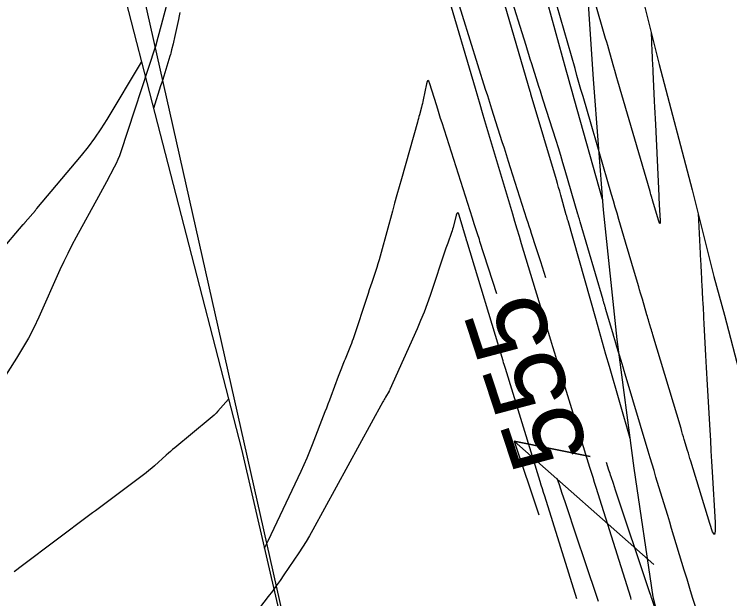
# Model space of a CAD drawing. Extents: x 954385 to 988206, y 1868364 to 1924553.
# Drawn here: x 957857.8 to 957913, y 1919566.3 to 1919611.4 of the extents above; entities that cross this region are included whole.
import ezdxf

# ---------------------------------------------------------------- set-up
doc = ezdxf.new("R2010")
doc.units = 0
for name, color, linetype in [('13', 7, 'Continuous'), ('16', 7, 'Continuous'), ('24', 7, 'Continuous'), ('26', 7, 'Continuous'), ('5', 7, 'Continuous'), ('6', 7, 'Continuous'), ('7', 7, 'Continuous'), ('Default', 7, 'Continuous')]:
    doc.layers.add(name, color=color, linetype=linetype)

msp = doc.modelspace()

# ---------------------------------------------------------------- linework, layer by layer
at = {"layer": '13'}
for points in [[(957852.935, 1919588.707), (957858.454, 1919595.175), (957858.462, 1919595.184), (957858.47, 1919595.193), (957858.478, 1919595.201), (957858.486, 1919595.21), (957858.52, 1919595.243), (957858.528, 1919595.252), (957858.536, 1919595.26), (957858.543, 1919595.27), (957858.55, 1919595.279), (957858.58, 1919595.319), (957858.587, 1919595.329), (957858.595, 1919595.339), (957858.602, 1919595.348), (957858.61, 1919595.358), (957859.394, 1919596.277), (957859.405, 1919596.289), (957859.414, 1919596.301), (957859.424, 1919596.313), (957859.433, 1919596.326), (957859.469, 1919596.377), (957859.479, 1919596.389), (957859.488, 1919596.402), (957859.498, 1919596.414), (957859.508, 1919596.426), (957862.946, 1919600.51), (957863.486, 1919601.177), (957863.997, 1919601.864), (957864.482, 1919602.57), (957864.938, 1919603.297), (957867.595, 1919607.714)], [(957874.297, 1919581.701), (957873.487, 1919580.766), (957873.349, 1919580.613), (957873.205, 1919580.467), (957873.055, 1919580.327), (957872.898, 1919580.193), (957870.15, 1919577.935), (957869.985, 1919577.798), (957869.821, 1919577.659), (957869.66, 1919577.518), (957869.499, 1919577.375), (957868.584, 1919576.55), (957868.376, 1919576.367), (957868.165, 1919576.188), (957867.949, 1919576.014), (957867.73, 1919575.844), (957866.108, 1919574.614), (957865.901, 1919574.458), (957865.693, 1919574.302), (957865.485, 1919574.147), (957865.277, 1919573.992), (957864.442, 1919573.375), (957864.233, 1919573.221), (957864.025, 1919573.066), (957863.817, 1919572.91), (957863.609, 1919572.755), (957858.39, 1919568.839), (957857.754, 1919568.363)]]:
    msp.add_lwpolyline(points, dxfattribs=at)
at = {"layer": '16'}
for points in [[(957890.519, 1919706.211), (957891.799, 1919696.25), (957893.016, 1919686.274), (957894.336, 1919676.322), (957895.78, 1919666.397), (957897.186, 1919656.464), (957898.672, 1919646.548), (957899.744, 1919636.541), (957900.425, 1919631.907), (957901.213, 1919626.621), (957901.79, 1919616.502), (957902.451, 1919606.402), (957903.226, 1919596.327), (957904.28, 1919586.315), (957905.605, 1919576.364), (957907.064, 1919566.442), (957908.777, 1919559.571)], [(957871.417, 1919619.226), (957868.747, 1919609.237), (957868.743, 1919609.221), (957868.739, 1919609.206), (957868.735, 1919609.19), (957868.732, 1919609.174), (957868.714, 1919609.093), (957868.711, 1919609.079), (957868.707, 1919609.065), (957868.7, 1919609.038), (957868.699, 1919609.031), (957868.697, 1919609.024), (957868.694, 1919609.018), (957868.692, 1919609.011), (957868.668, 1919608.946), (957868.663, 1919608.933), (957868.659, 1919608.92), (957868.654, 1919608.907), (957868.65, 1919608.894), (957865.986, 1919600.8), (957865.879, 1919600.496), (957865.76, 1919600.198), (957865.628, 1919599.905), (957865.485, 1919599.617), (957864.886, 1919598.476), (957864.736, 1919598.191), (957864.584, 1919597.907), (957864.431, 1919597.623), (957864.276, 1919597.341), (957862.547, 1919594.206), (957862.213, 1919593.586), (957861.892, 1919592.96), (957861.585, 1919592.327), (957861.291, 1919591.688), (957859.653, 1919588.031), (957859.269, 1919587.215), (957858.856, 1919586.415), (957858.414, 1919585.63), (957857.943, 1919584.862), (957851.753, 1919575.167)], [(957905.301, 1919578.651), (957903.706, 1919584.213), (957903.44, 1919585.14), (957903.176, 1919586.067), (957902.912, 1919586.995), (957902.649, 1919587.922), (957900.516, 1919595.465), (957900.482, 1919595.584), (957900.449, 1919595.704), (957900.415, 1919595.823), (957900.382, 1919595.943), (957899.957, 1919597.465), (957899.875, 1919597.758), (957899.791, 1919598.051), (957899.706, 1919598.344), (957899.62, 1919598.636), (957897.675, 1919605.178), (957897.654, 1919605.249), (957897.633, 1919605.321), (957897.612, 1919605.392), (957897.591, 1919605.464), (957894.933, 1919614.566)], [(957903.165, 1919597.117), (957900.994, 1919604.901), (957900.841, 1919605.453), (957900.687, 1919606.006), (957900.534, 1919606.559), (957900.382, 1919607.112), (957898.392, 1919614.352)], [(957905.396, 1919566.225), (957905.35, 1919566.371), (957902.683, 1919574.885), (957902.563, 1919575.269), (957902.443, 1919575.654), (957902.324, 1919576.039), (957902.205, 1919576.424), (957899.805, 1919584.218), (957899.648, 1919584.729), (957899.492, 1919585.24), (957899.336, 1919585.752), (957899.181, 1919586.264), (957896.934, 1919593.686), (957896.761, 1919594.262), (957896.588, 1919594.837), (957896.415, 1919595.413), (957896.244, 1919595.99), (957894.101, 1919603.195), (957893.916, 1919603.82), (957893.732, 1919604.445), (957893.548, 1919605.07), (957893.365, 1919605.696), (957891.193, 1919613.133)], [(957901.201, 1919566.282), (957898.715, 1919574.217), (957898.627, 1919574.498), (957898.54, 1919574.778), (957898.453, 1919575.059), (957898.366, 1919575.34), (957895.679, 1919584.066), (957895.633, 1919584.215), (957895.588, 1919584.364), (957895.542, 1919584.514), (957895.497, 1919584.663), (957892.697, 1919593.915), (957892.683, 1919593.961), (957892.67, 1919594.007), (957892.106, 1919595.902), (957892.048, 1919596.051), (957891.991, 1919596.1), (957891.936, 1919596.049), (957891.882, 1919595.898), (957891.637, 1919594.965), (957891.6, 1919594.828), (957891.559, 1919594.692), (957891.515, 1919594.558), (957891.469, 1919594.424), (957891.276, 1919593.89), (957891.228, 1919593.757), (957891.181, 1919593.623), (957891.135, 1919593.489), (957891.089, 1919593.355), (957889.865, 1919589.705), (957889.638, 1919589.055), (957889.396, 1919588.411), (957889.138, 1919587.773), (957888.865, 1919587.142), (957886.764, 1919582.444), (957886.748, 1919582.411), (957886.732, 1919582.378), (957886.715, 1919582.346), (957886.697, 1919582.314), (957886.428, 1919581.841), (957886.377, 1919581.752), (957886.327, 1919581.662), (957886.277, 1919581.572), (957886.227, 1919581.482), (957880.817, 1919571.595), (957880.564, 1919571.146), (957880.3, 1919570.702), (957880.027, 1919570.265), (957879.742, 1919569.835), (957878.584, 1919568.125), (957878.292, 1919567.7), (957877.993, 1919567.279), (957877.688, 1919566.863), (957877.377, 1919566.451), (957872.504, 1919560.096)]]:
    msp.add_lwpolyline(points, dxfattribs=at)
at = {"layer": '24'}
for points in [[(957817.372, 1919769.232), (957831.573, 1919731.267), (957843.682, 1919693.162), (957854.383, 1919657.846), (957864.753, 1919618.743), (957875.296, 1919577.825), (957884.584, 1919537.635), (957892.533, 1919502.268), (957902.065, 1919460.502), (957910.491, 1919421.742), (957920.001, 1919379.492)], [(957892.09, 1919706.564), (957893.285, 1919696.583), (957894.589, 1919686.627), (957895.913, 1919676.676), (957897.289, 1919666.736), (957898.653, 1919656.793), (957899.988, 1919646.844), (957901.581, 1919636.953), (957903.073, 1919627.039), (957905.12, 1919617.249), (957907.548, 1919607.546), (957910.107, 1919597.871), (957911.76, 1919591.16), (957912.581, 1919588.178), (957915.105, 1919578.495)]]:
    msp.add_lwpolyline(points, dxfattribs=at)
at = {"layer": '26'}
msp.add_lwpolyline([(957907.131, 1919568.928), (957896.35, 1919578.451), (957902.231, 1919577.259), (957896.35, 1919578.451), (957898.258, 1919572.762)], dxfattribs=at)
at = {"layer": '6'}
for points in [[(957895.022, 1919589.825), (957893.715, 1919593.869), (957893.667, 1919594.02), (957893.618, 1919594.171), (957893.57, 1919594.322), (957893.521, 1919594.474), (957893.28, 1919595.23), (957893.135, 1919595.684), (957890.794, 1919603.031), (957890.682, 1919603.383), (957890.57, 1919603.736), (957890.459, 1919604.088), (957890.348, 1919604.441), (957889.84, 1919606.064), (957889.766, 1919606.248), (957889.699, 1919606.307), (957889.637, 1919606.241), (957889.583, 1919606.05), (957889.332, 1919604.822), (957889.301, 1919604.676), (957889.269, 1919604.531), (957889.234, 1919604.386), (957889.197, 1919604.242), (957889.046, 1919603.665), (957889.008, 1919603.521), (957888.969, 1919603.377), (957888.93, 1919603.233), (957888.889, 1919603.09), (957887.654, 1919598.721), (957887.477, 1919598.095), (957887.303, 1919597.468), (957887.129, 1919596.841), (957886.958, 1919596.214), (957886.094, 1919593.034), (957886.012, 1919592.741), (957885.926, 1919592.449), (957885.837, 1919592.158), (957885.744, 1919591.869), (957885.363, 1919590.713), (957885.268, 1919590.424), (957885.172, 1919590.135), (957885.077, 1919589.846), (957884.982, 1919589.557), (957883.981, 1919586.524), (957883.921, 1919586.346), (957883.858, 1919586.169), (957883.792, 1919585.993), (957883.723, 1919585.819), (957883.409, 1919585.041), (957883.355, 1919584.908), (957883.3, 1919584.774), (957883.245, 1919584.641), (957883.19, 1919584.507), (957882.97, 1919583.974), (957882.915, 1919583.841), (957882.862, 1919583.707), (957882.811, 1919583.572), (957882.76, 1919583.437), (957882.202, 1919581.91), (957882.092, 1919581.611), (957881.98, 1919581.312), (957881.867, 1919581.014), (957881.753, 1919580.716), (957880.775, 1919578.177), (957880.569, 1919577.657), (957880.353, 1919577.141), (957880.128, 1919576.629), (957879.893, 1919576.121), (957877.34, 1919570.73), (957877.19, 1919570.412), (957877.068, 1919570.156)], [(957902.861, 1919566.074), (957902.682, 1919566.608), (957901.967, 1919568.747), (957901.788, 1919569.281), (957901.609, 1919569.816), (957901.43, 1919570.35), (957901.252, 1919570.885), (957900.29, 1919573.758), (957900.071, 1919574.415), (957899.852, 1919575.073), (957899.688, 1919575.569)]]:
    msp.add_lwpolyline(points, dxfattribs=at)
at = {"layer": '7'}
for points in [[(957906.922, 1919610.047), (957906.954, 1919609.33), (957906.959, 1919609.211), (957906.965, 1919609.091), (957906.97, 1919608.972), (957906.975, 1919608.852), (957907.02, 1919607.847), (957907.03, 1919607.639), (957907.04, 1919607.432), (957907.049, 1919607.224), (957907.059, 1919607.017), (957907.172, 1919604.712), (957907.194, 1919604.259), (957907.216, 1919603.806), (957907.238, 1919603.352), (957907.26, 1919602.899), (957907.525, 1919597.405), (957907.528, 1919597.349), (957907.531, 1919597.293), (957907.533, 1919597.237), (957907.536, 1919597.182), (957907.553, 1919596.847), (957907.559, 1919596.735), (957907.624, 1919595.469), (957907.626, 1919595.296), (957907.61, 1919595.235), (957907.573, 1919595.287), (957907.518, 1919595.451), (957907.043, 1919597.066), (957907.026, 1919597.121), (957907.01, 1919597.176), (957906.994, 1919597.231), (957906.978, 1919597.286), (957906.914, 1919597.507), (957906.882, 1919597.617), (957906.85, 1919597.727), (957904.37, 1919606.246), (957904.29, 1919606.521), (957904.21, 1919606.797), (957904.13, 1919607.072), (957904.051, 1919607.348), (957903.735, 1919608.451), (957903.656, 1919608.727), (957903.577, 1919609.002), (957903.498, 1919609.278), (957903.419, 1919609.554), (957901.711, 1919615.503)], [(957898.808, 1919591.064), (957898.409, 1919592.297), (957898.231, 1919592.847), (957898.054, 1919593.397), (957897.698, 1919594.497), (957897.61, 1919594.772), (957897.521, 1919595.047), (957897.433, 1919595.322), (957897.345, 1919595.597), (957896.084, 1919599.555), (957895.923, 1919600.06), (957895.762, 1919600.566), (957895.6, 1919601.072), (957895.439, 1919601.577), (957894.794, 1919603.6), (957894.634, 1919604.106), (957894.473, 1919604.612), (957894.314, 1919605.118), (957894.155, 1919605.624), (957891.767, 1919613.256)], [(957910.343, 1919565.678), (957910.127, 1919566.38), (957909.913, 1919567.082), (957909.699, 1919567.784), (957909.486, 1919568.486), (957908.511, 1919571.706), (957908.36, 1919572.203), (957908.21, 1919572.7), (957908.059, 1919573.197), (957907.908, 1919573.694), (957907.304, 1919575.683), (957907.153, 1919576.18), (957907.003, 1919576.677), (957906.854, 1919577.175), (957906.705, 1919577.673), (957904.926, 1919583.629), (957904.847, 1919583.894), (957904.768, 1919584.159), (957904.688, 1919584.425), (957904.609, 1919584.69), (957904.291, 1919585.751), (957904.212, 1919586.017), (957904.133, 1919586.282), (957904.054, 1919586.547), (957903.975, 1919586.813), (957903.414, 1919588.712), (957903.398, 1919588.766), (957903.382, 1919588.82), (957903.366, 1919588.874), (957903.35, 1919588.928), (957903.286, 1919589.143), (957903.27, 1919589.197), (957903.254, 1919589.251), (957903.238, 1919589.305), (957903.222, 1919589.359), (957901.448, 1919595.401), (957901.419, 1919595.5), (957901.39, 1919595.599), (957901.331, 1919595.797), (957901.317, 1919595.846), (957901.302, 1919595.896), (957901.288, 1919595.945), (957901.273, 1919595.995), (957900.294, 1919599.368), (957900.124, 1919599.946), (957899.95, 1919600.523), (957899.773, 1919601.099), (957899.592, 1919601.673), (957898.601, 1919604.783), (957898.489, 1919605.135), (957898.377, 1919605.488), (957898.266, 1919605.84), (957898.155, 1919606.193), (957897.713, 1919607.604), (957897.602, 1919607.957), (957897.492, 1919608.309), (957897.382, 1919608.662), (957897.271, 1919609.015), (957895.907, 1919613.375)], [(957910.556, 1919596.049), (957910.715, 1919592.944), (957910.725, 1919592.745), (957910.735, 1919592.545), (957910.746, 1919592.346), (957910.756, 1919592.146), (957910.797, 1919591.348), (957910.807, 1919591.148), (957910.818, 1919590.949), (957910.828, 1919590.749), (957910.839, 1919590.549), (957910.9, 1919589.39), (957910.916, 1919589.076), (957910.933, 1919588.762), (957910.966, 1919588.133), (957910.975, 1919587.976), (957910.983, 1919587.819), (957910.992, 1919587.662), (957911, 1919587.505), (957911.136, 1919585.071), (957911.161, 1919584.613), (957911.186, 1919584.155), (957911.212, 1919583.696), (957911.237, 1919583.238), (957911.455, 1919579.311), (957911.501, 1919578.504), (957911.546, 1919577.697), (957911.593, 1919576.889), (957911.64, 1919576.082), (957911.871, 1919572.178), (957911.885, 1919571.493), (957911.82, 1919571.252), (957911.675, 1919571.455), (957911.45, 1919572.102), (957909.993, 1919576.9), (957909.929, 1919577.11), (957909.866, 1919577.32), (957909.803, 1919577.53), (957909.74, 1919577.74), (957909.489, 1919578.581), (957909.426, 1919578.791), (957909.363, 1919579.002), (957909.3, 1919579.212), (957909.237, 1919579.422), (957907.068, 1919586.665), (957907.029, 1919586.794), (957906.991, 1919586.923), (957906.952, 1919587.053), (957906.914, 1919587.182), (957906.761, 1919587.701), (957906.723, 1919587.83), (957906.684, 1919587.96), (957906.646, 1919588.089), (957906.607, 1919588.219), (957906.254, 1919589.409), (957906.182, 1919589.651), (957906.11, 1919589.892), (957906.039, 1919590.134), (957905.968, 1919590.376), (957905.492, 1919591.995), (957905.39, 1919592.346), (957905.286, 1919592.696), (957905.183, 1919593.046), (957905.08, 1919593.397), (957904.439, 1919595.576), (957904.298, 1919596.056), (957904.157, 1919596.536), (957904.017, 1919597.017), (957903.877, 1919597.497), (957902.918, 1919600.798), (957902.763, 1919601.334), (957902.607, 1919601.87), (957902.451, 1919602.406), (957902.295, 1919602.942), (957901.671, 1919605.085), (957901.515, 1919605.621), (957901.36, 1919606.157), (957901.206, 1919606.693), (957901.052, 1919607.229), (957899.646, 1919612.134)], [(957870.557, 1919611.565), (957870.496, 1919611.293), (957870.436, 1919611.021), (957870.137, 1919609.628), (957870.111, 1919609.508), (957870.084, 1919609.388), (957870.056, 1919609.268), (957870.028, 1919609.148), (957869.914, 1919608.669), (957869.884, 1919608.549), (957869.852, 1919608.43), (957869.819, 1919608.312), (957869.783, 1919608.194), (957869.382, 1919606.907), (957869.303, 1919606.653), (957869.224, 1919606.399), (957869.145, 1919606.145), (957869.066, 1919605.892), (957868.517, 1919604.135)], [(957907.736, 1919564.084), (957906.981, 1919566.303), (957906.962, 1919566.359), (957906.943, 1919566.415), (957906.924, 1919566.47), (957906.906, 1919566.526), (957906.812, 1919566.806), (957906.756, 1919566.973), (957904.185, 1919574.659), (957904.012, 1919575.175), (957903.84, 1919575.691), (957903.797, 1919575.819), (957903.754, 1919575.948), (957903.711, 1919576.077), (957903.669, 1919576.206), (957903.471, 1919576.807)]]:
    msp.add_lwpolyline(points, dxfattribs=at)
at = {"layer": 'Default'}
msp.add_line((958200.602, 1918129.717), (957843.865, 1919719.405), dxfattribs=at)

# ---------------------------------------------------------------- texts
at = {"layer": '5'}
msp.add_text('555', height=6, rotation=108.1235, dxfattribs=at).set_placement((957902.206, 1919577.521))

doc.saveas('drawing.dxf')
